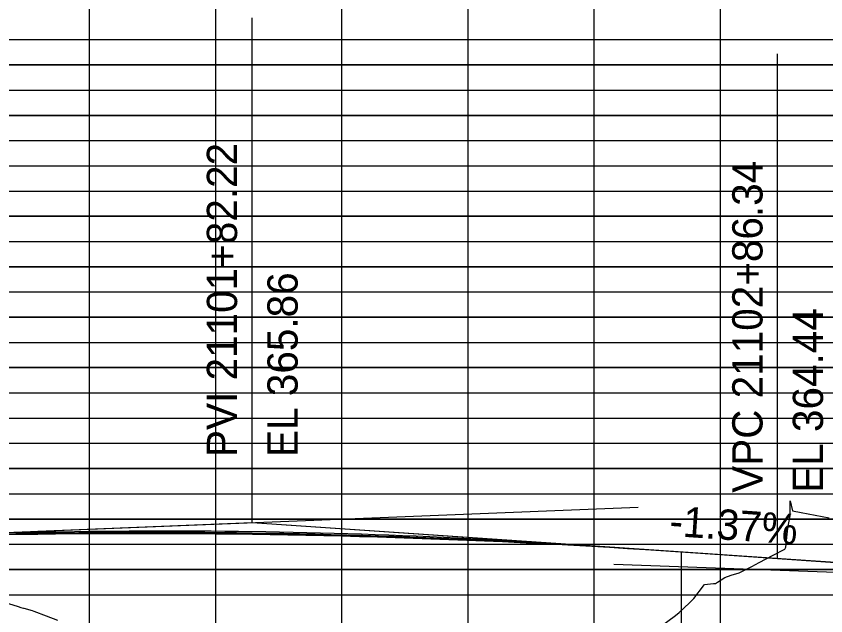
# Model space of a CAD drawing. Extents: x 1195880 to 1289360, y 2059330 to 2086925.
# Drawn here: x 1197141.8 to 1197302.3, y 2059661.6 to 2059780.4 of the extents above; entities that cross this region are included whole.
import ezdxf

# ---------------------------------------------------------------- set-up
doc = ezdxf.new("R2010")
doc.units = 0
for name, color, linetype in [('Default', 7, 'Continuous'), ('Existing Ground PGL', 7, 'Continuous'), ('Grid', 7, 'Continuous'), ('Profile', 7, 'Continuous'), ('Profile Annotation', 7, 'Continuous')]:
    doc.layers.add(name, color=color, linetype=linetype)

msp = doc.modelspace()

# ---------------------------------------------------------------- linework, layer by layer
for p, q in [((1197087.81, 2059676.01), (1197188.59, 2059680.04)), ((1197087.81, 2059676.01), (1197188.59, 2059680.04)), ((1197188.59, 2059680.04), (1197367.71, 2059667.81)), ((1197188.59, 2059680.04), (1197367.71, 2059667.81)), ((1197253.56, 2059675.6), (1197367.71, 2059667.81)), ((1197253.56, 2059675.6), (1197326.4, 2059670.63)), ((1197253.56, 2059675.6), (1197317.71, 2059671.22)), ((1197253.56, 2059675.6), (1197323.22, 2059670.85)), ((1197253.56, 2059675.6), (1197322.71, 2059670.88)), ((1197253.56, 2059675.6), (1197317.71, 2059671.22)), ((1197253.56, 2059675.6), (1197320.21, 2059671.05)), ((1197263.59, 2059674.92), (1197320.21, 2059671.05)), ((1197268.59, 2059674.58), (1197320.21, 2059671.05)), ((1197273.59, 2059674.23), (1197320.21, 2059671.05)), ((1197273.59, 2059674.23), (1197307.21, 2059671.94)), ((1197273.59, 2059674.23), (1197305.21, 2059672.08)), ((1197273.59, 2059674.23), (1197302.71, 2059672.25)), ((1197273.59, 2059674.23), (1197300.21, 2059672.42)), ((1197273.59, 2059674.23), (1197297.71, 2059672.59)), ((1197273.59, 2059674.23), (1197296.2, 2059672.69)), ((1197273.59, 2059674.23), (1197295.21, 2059672.76)), ((1197273.59, 2059674.23), (1197292.71, 2059672.93))]:
    msp.add_line(p, q)
for points in [[(1197138.59, 2059677.73), (1197141.92, 2059677.8), (1197145.26, 2059677.85), (1197148.59, 2059677.9), (1197151.92, 2059677.94), (1197155.26, 2059677.97), (1197158.59, 2059677.99), (1197161.92, 2059678.01), (1197165.26, 2059678.02), (1197168.59, 2059678.02), (1197171.92, 2059678.01), (1197175.26, 2059678), (1197178.59, 2059677.98), (1197181.92, 2059677.95), (1197185.26, 2059677.92), (1197191.92, 2059677.82), (1197195.26, 2059677.76), (1197198.59, 2059677.7), (1197201.92, 2059677.62), (1197205.26, 2059677.54), (1197208.59, 2059677.45), (1197211.92, 2059677.36), (1197215.26, 2059677.25), (1197218.59, 2059677.14), (1197221.92, 2059677.03), (1197225.26, 2059676.9), (1197228.59, 2059676.77), (1197231.92, 2059676.62), (1197235.26, 2059676.48), (1197238.59, 2059676.32), (1197241.92, 2059676.16), (1197245.26, 2059675.98), (1197248.59, 2059675.81), (1197251.92, 2059675.62), (1197255.26, 2059675.43), (1197258.59, 2059675.22), (1197261.92, 2059675.02), (1197265.26, 2059674.8), (1197268.59, 2059674.58)], [(1197139.01, 2059677.66), (1197142.55, 2059677.71), (1197146.09, 2059677.76), (1197149.63, 2059677.8), (1197153.17, 2059677.84), (1197156.71, 2059677.86), (1197160.26, 2059677.88), (1197163.8, 2059677.89), (1197167.34, 2059677.89), (1197170.88, 2059677.89), (1197174.42, 2059677.87), (1197177.96, 2059677.85), (1197181.51, 2059677.82), (1197185.05, 2059677.78), (1197192.13, 2059677.68), (1197195.67, 2059677.62), (1197199.21, 2059677.55), (1197202.76, 2059677.47), (1197206.3, 2059677.39), (1197209.84, 2059677.29), (1197213.38, 2059677.19), (1197216.92, 2059677.08), (1197220.46, 2059676.96), (1197224.01, 2059676.84), (1197227.55, 2059676.7), (1197231.09, 2059676.56), (1197234.63, 2059676.41), (1197238.17, 2059676.25), (1197241.71, 2059676.09), (1197245.26, 2059675.91), (1197248.8, 2059675.73), (1197252.34, 2059675.54), (1197255.88, 2059675.34), (1197259.42, 2059675.14), (1197262.96, 2059674.92), (1197266.51, 2059674.7), (1197270.05, 2059674.47), (1197273.59, 2059674.23)], [(1197139.01, 2059677.66), (1197142.55, 2059677.71), (1197146.09, 2059677.76), (1197149.63, 2059677.8), (1197153.17, 2059677.84), (1197156.71, 2059677.86), (1197160.26, 2059677.88), (1197163.8, 2059677.89), (1197167.34, 2059677.89), (1197170.88, 2059677.89), (1197174.42, 2059677.87), (1197177.96, 2059677.85), (1197181.51, 2059677.82), (1197185.05, 2059677.78), (1197192.13, 2059677.68), (1197195.67, 2059677.62), (1197199.21, 2059677.55), (1197202.76, 2059677.47), (1197206.3, 2059677.39), (1197209.84, 2059677.29), (1197213.38, 2059677.19), (1197216.92, 2059677.08), (1197220.46, 2059676.96), (1197224.01, 2059676.84), (1197227.55, 2059676.7), (1197231.09, 2059676.56), (1197234.63, 2059676.41), (1197238.17, 2059676.25), (1197241.71, 2059676.09), (1197245.26, 2059675.91), (1197248.8, 2059675.73), (1197252.34, 2059675.54), (1197255.88, 2059675.34), (1197259.42, 2059675.14), (1197262.96, 2059674.92), (1197266.51, 2059674.7), (1197270.05, 2059674.47), (1197273.59, 2059674.23)], [(1197139.01, 2059677.66), (1197142.55, 2059677.71), (1197146.09, 2059677.76), (1197149.63, 2059677.8), (1197153.17, 2059677.84), (1197156.71, 2059677.86), (1197160.26, 2059677.88), (1197163.8, 2059677.89), (1197167.34, 2059677.89), (1197170.88, 2059677.89), (1197174.42, 2059677.87), (1197177.96, 2059677.85), (1197181.51, 2059677.82), (1197185.05, 2059677.78), (1197192.13, 2059677.68), (1197195.67, 2059677.62), (1197199.21, 2059677.55), (1197202.76, 2059677.47), (1197206.3, 2059677.39), (1197209.84, 2059677.29), (1197213.38, 2059677.19), (1197216.92, 2059677.08), (1197220.46, 2059676.96), (1197224.01, 2059676.84), (1197227.55, 2059676.7), (1197231.09, 2059676.56), (1197234.63, 2059676.41), (1197238.17, 2059676.25), (1197241.71, 2059676.09), (1197245.26, 2059675.91), (1197248.8, 2059675.73), (1197252.34, 2059675.54), (1197255.88, 2059675.34), (1197259.42, 2059675.14), (1197262.96, 2059674.92), (1197266.51, 2059674.7), (1197270.05, 2059674.47), (1197273.59, 2059674.23)], [(1197139.01, 2059677.66), (1197142.55, 2059677.71), (1197146.09, 2059677.76), (1197149.63, 2059677.8), (1197153.17, 2059677.84), (1197156.71, 2059677.86), (1197160.26, 2059677.88), (1197163.8, 2059677.89), (1197167.34, 2059677.89), (1197170.88, 2059677.89), (1197174.42, 2059677.87), (1197177.96, 2059677.85), (1197181.51, 2059677.82), (1197185.05, 2059677.78), (1197192.13, 2059677.68), (1197195.67, 2059677.62), (1197199.21, 2059677.55), (1197202.76, 2059677.47), (1197206.3, 2059677.39), (1197209.84, 2059677.29), (1197213.38, 2059677.19), (1197216.92, 2059677.08), (1197220.46, 2059676.96), (1197224.01, 2059676.84), (1197227.55, 2059676.7), (1197231.09, 2059676.56), (1197234.63, 2059676.41), (1197238.17, 2059676.25), (1197241.71, 2059676.09), (1197245.26, 2059675.91), (1197248.8, 2059675.73), (1197252.34, 2059675.54), (1197255.88, 2059675.34), (1197259.42, 2059675.14), (1197262.96, 2059674.92), (1197266.51, 2059674.7), (1197270.05, 2059674.47), (1197273.59, 2059674.23)], [(1197139.01, 2059677.66), (1197142.55, 2059677.71), (1197146.09, 2059677.76), (1197149.63, 2059677.8), (1197153.17, 2059677.84), (1197156.71, 2059677.86), (1197160.26, 2059677.88), (1197163.8, 2059677.89), (1197167.34, 2059677.89), (1197170.88, 2059677.89), (1197174.42, 2059677.87), (1197177.96, 2059677.85), (1197181.51, 2059677.82), (1197185.05, 2059677.78), (1197192.13, 2059677.68), (1197195.67, 2059677.62), (1197199.21, 2059677.55), (1197202.76, 2059677.47), (1197206.3, 2059677.39), (1197209.84, 2059677.29), (1197213.38, 2059677.19), (1197216.92, 2059677.08), (1197220.46, 2059676.96), (1197224.01, 2059676.84), (1197227.55, 2059676.7), (1197231.09, 2059676.56), (1197234.63, 2059676.41), (1197238.17, 2059676.25), (1197241.71, 2059676.09), (1197245.26, 2059675.91), (1197248.8, 2059675.73), (1197252.34, 2059675.54), (1197255.88, 2059675.34), (1197259.42, 2059675.14), (1197262.96, 2059674.92), (1197266.51, 2059674.7), (1197270.05, 2059674.47), (1197273.59, 2059674.23)], [(1197139.01, 2059677.66), (1197142.55, 2059677.71), (1197146.09, 2059677.76), (1197149.63, 2059677.8), (1197153.17, 2059677.84), (1197156.71, 2059677.86), (1197160.26, 2059677.88), (1197163.8, 2059677.89), (1197167.34, 2059677.89), (1197170.88, 2059677.89), (1197174.42, 2059677.87), (1197177.96, 2059677.85), (1197181.51, 2059677.82), (1197185.05, 2059677.78), (1197192.13, 2059677.68), (1197195.67, 2059677.62), (1197199.21, 2059677.55), (1197202.76, 2059677.47), (1197206.3, 2059677.39), (1197209.84, 2059677.29), (1197213.38, 2059677.19), (1197216.92, 2059677.08), (1197220.46, 2059676.96), (1197224.01, 2059676.84), (1197227.55, 2059676.7), (1197231.09, 2059676.56), (1197234.63, 2059676.41), (1197238.17, 2059676.25), (1197241.71, 2059676.09), (1197245.26, 2059675.91), (1197248.8, 2059675.73), (1197252.34, 2059675.54), (1197255.88, 2059675.34), (1197259.42, 2059675.14), (1197262.96, 2059674.92), (1197266.51, 2059674.7), (1197270.05, 2059674.47), (1197273.59, 2059674.23)], [(1197139.01, 2059677.66), (1197142.55, 2059677.71), (1197146.09, 2059677.76), (1197149.63, 2059677.8), (1197153.17, 2059677.84), (1197156.71, 2059677.86), (1197160.26, 2059677.88), (1197163.8, 2059677.89), (1197167.34, 2059677.89), (1197170.88, 2059677.89), (1197174.42, 2059677.87), (1197177.96, 2059677.85), (1197181.51, 2059677.82), (1197185.05, 2059677.78), (1197192.13, 2059677.68), (1197195.67, 2059677.62), (1197199.21, 2059677.55), (1197202.76, 2059677.47), (1197206.3, 2059677.39), (1197209.84, 2059677.29), (1197213.38, 2059677.19), (1197216.92, 2059677.08), (1197220.46, 2059676.96), (1197224.01, 2059676.84), (1197227.55, 2059676.7), (1197231.09, 2059676.56), (1197234.63, 2059676.41), (1197238.17, 2059676.25), (1197241.71, 2059676.09), (1197245.26, 2059675.91), (1197248.8, 2059675.73), (1197252.34, 2059675.54), (1197255.88, 2059675.34), (1197259.42, 2059675.14), (1197262.96, 2059674.92), (1197266.51, 2059674.7), (1197270.05, 2059674.47), (1197273.59, 2059674.23)], [(1197139.01, 2059677.66), (1197142.55, 2059677.71), (1197146.09, 2059677.76), (1197149.63, 2059677.8), (1197153.17, 2059677.84), (1197156.71, 2059677.86), (1197160.26, 2059677.88), (1197163.8, 2059677.89), (1197167.34, 2059677.89), (1197170.88, 2059677.89), (1197174.42, 2059677.87), (1197177.96, 2059677.85), (1197181.51, 2059677.82), (1197185.05, 2059677.78), (1197192.13, 2059677.68), (1197195.67, 2059677.62), (1197199.21, 2059677.55), (1197202.76, 2059677.47), (1197206.3, 2059677.39), (1197209.84, 2059677.29), (1197213.38, 2059677.19), (1197216.92, 2059677.08), (1197220.46, 2059676.96), (1197224.01, 2059676.84), (1197227.55, 2059676.7), (1197231.09, 2059676.56), (1197234.63, 2059676.41), (1197238.17, 2059676.25), (1197241.71, 2059676.09), (1197245.26, 2059675.91), (1197248.8, 2059675.73), (1197252.34, 2059675.54), (1197255.88, 2059675.34), (1197259.42, 2059675.14), (1197262.96, 2059674.92), (1197266.51, 2059674.7), (1197270.05, 2059674.47), (1197273.59, 2059674.23)], [(1197139.01, 2059677.66), (1197142.55, 2059677.71), (1197146.09, 2059677.76), (1197149.63, 2059677.8), (1197153.17, 2059677.84), (1197156.71, 2059677.86), (1197160.26, 2059677.88), (1197163.8, 2059677.89), (1197167.34, 2059677.89), (1197170.88, 2059677.89), (1197174.42, 2059677.87), (1197177.96, 2059677.85), (1197181.51, 2059677.82), (1197185.05, 2059677.78), (1197192.13, 2059677.68), (1197195.67, 2059677.62), (1197199.21, 2059677.55), (1197202.76, 2059677.47), (1197206.3, 2059677.39), (1197209.84, 2059677.29), (1197213.38, 2059677.19), (1197216.92, 2059677.08), (1197220.46, 2059676.96), (1197224.01, 2059676.84), (1197227.55, 2059676.7), (1197231.09, 2059676.56), (1197234.63, 2059676.41), (1197238.17, 2059676.25), (1197241.71, 2059676.09), (1197245.26, 2059675.91), (1197248.8, 2059675.73), (1197252.34, 2059675.54), (1197255.88, 2059675.34), (1197259.42, 2059675.14), (1197262.96, 2059674.92), (1197266.51, 2059674.7), (1197270.05, 2059674.47), (1197273.59, 2059674.23)], [(1197139.86, 2059677.98), (1197142.57, 2059678.05), (1197145.28, 2059678.11), (1197147.98, 2059678.17), (1197150.69, 2059678.22), (1197153.4, 2059678.26), (1197156.11, 2059678.3), (1197158.81, 2059678.33), (1197161.52, 2059678.36), (1197164.23, 2059678.38), (1197166.93, 2059678.39), (1197169.64, 2059678.4), (1197172.35, 2059678.4), (1197175.05, 2059678.39), (1197177.76, 2059678.38), (1197180.47, 2059678.37), (1197183.18, 2059678.34), (1197185.88, 2059678.31), (1197191.3, 2059678.24), (1197194, 2059678.19), (1197196.71, 2059678.14), (1197199.42, 2059678.08), (1197202.12, 2059678.01), (1197204.83, 2059677.94), (1197207.54, 2059677.86), (1197210.25, 2059677.78), (1197212.95, 2059677.69), (1197215.66, 2059677.59), (1197218.37, 2059677.49), (1197221.07, 2059677.38), (1197223.78, 2059677.27), (1197226.49, 2059677.15), (1197229.19, 2059677.02), (1197231.9, 2059676.89), (1197234.61, 2059676.75), (1197237.32, 2059676.6), (1197240.02, 2059676.45), (1197242.73, 2059676.29), (1197245.44, 2059676.13), (1197248.14, 2059675.96), (1197250.85, 2059675.78), (1197253.56, 2059675.6)], [(1197139.86, 2059677.98), (1197142.57, 2059678.05), (1197145.28, 2059678.11), (1197147.98, 2059678.17), (1197150.69, 2059678.22), (1197153.4, 2059678.26), (1197156.11, 2059678.3), (1197158.81, 2059678.33), (1197161.52, 2059678.36), (1197164.23, 2059678.38), (1197166.93, 2059678.39), (1197169.64, 2059678.4), (1197172.35, 2059678.4), (1197175.05, 2059678.39), (1197177.76, 2059678.38), (1197180.47, 2059678.37), (1197183.18, 2059678.34), (1197185.88, 2059678.31), (1197191.3, 2059678.24), (1197194, 2059678.19), (1197196.71, 2059678.14), (1197199.42, 2059678.08), (1197202.12, 2059678.01), (1197204.83, 2059677.94), (1197207.54, 2059677.86), (1197210.25, 2059677.78), (1197212.95, 2059677.69), (1197215.66, 2059677.59), (1197218.37, 2059677.49), (1197221.07, 2059677.38), (1197223.78, 2059677.27), (1197226.49, 2059677.15), (1197229.19, 2059677.02), (1197231.9, 2059676.89), (1197234.61, 2059676.75), (1197237.32, 2059676.6), (1197240.02, 2059676.45), (1197242.73, 2059676.29), (1197245.44, 2059676.13), (1197248.14, 2059675.96), (1197250.85, 2059675.78), (1197253.56, 2059675.6)], [(1197139.86, 2059677.98), (1197142.57, 2059678.05), (1197145.28, 2059678.11), (1197147.98, 2059678.17), (1197150.69, 2059678.22), (1197153.4, 2059678.26), (1197156.11, 2059678.3), (1197158.81, 2059678.33), (1197161.52, 2059678.36), (1197164.23, 2059678.38), (1197166.93, 2059678.39), (1197169.64, 2059678.4), (1197172.35, 2059678.4), (1197175.05, 2059678.39), (1197177.76, 2059678.38), (1197180.47, 2059678.37), (1197183.18, 2059678.34), (1197185.88, 2059678.31), (1197191.3, 2059678.24), (1197194, 2059678.19), (1197196.71, 2059678.14), (1197199.42, 2059678.08), (1197202.12, 2059678.01), (1197204.83, 2059677.94), (1197207.54, 2059677.86), (1197210.25, 2059677.78), (1197212.95, 2059677.69), (1197215.66, 2059677.59), (1197218.37, 2059677.49), (1197221.07, 2059677.38), (1197223.78, 2059677.27), (1197226.49, 2059677.15), (1197229.19, 2059677.02), (1197231.9, 2059676.89), (1197234.61, 2059676.75), (1197237.32, 2059676.6), (1197240.02, 2059676.45), (1197242.73, 2059676.29), (1197245.44, 2059676.13), (1197248.14, 2059675.96), (1197250.85, 2059675.78), (1197253.56, 2059675.6)], [(1197139.86, 2059677.98), (1197142.57, 2059678.05), (1197145.28, 2059678.11), (1197147.98, 2059678.17), (1197150.69, 2059678.22), (1197153.4, 2059678.26), (1197156.11, 2059678.3), (1197158.81, 2059678.33), (1197161.52, 2059678.36), (1197164.23, 2059678.38), (1197166.93, 2059678.39), (1197169.64, 2059678.4), (1197172.35, 2059678.4), (1197175.05, 2059678.39), (1197177.76, 2059678.38), (1197180.47, 2059678.37), (1197183.18, 2059678.34), (1197185.88, 2059678.31), (1197191.3, 2059678.24), (1197194, 2059678.19), (1197196.71, 2059678.14), (1197199.42, 2059678.08), (1197202.12, 2059678.01), (1197204.83, 2059677.94), (1197207.54, 2059677.86), (1197210.25, 2059677.78), (1197212.95, 2059677.69), (1197215.66, 2059677.59), (1197218.37, 2059677.49), (1197221.07, 2059677.38), (1197223.78, 2059677.27), (1197226.49, 2059677.15), (1197229.19, 2059677.02), (1197231.9, 2059676.89), (1197234.61, 2059676.75), (1197237.32, 2059676.6), (1197240.02, 2059676.45), (1197242.73, 2059676.29), (1197245.44, 2059676.13), (1197248.14, 2059675.96), (1197250.85, 2059675.78), (1197253.56, 2059675.6)], [(1197139.86, 2059677.98), (1197142.57, 2059678.05), (1197145.28, 2059678.11), (1197147.98, 2059678.17), (1197150.69, 2059678.22), (1197153.4, 2059678.26), (1197156.11, 2059678.3), (1197158.81, 2059678.33), (1197161.52, 2059678.36), (1197164.23, 2059678.38), (1197166.93, 2059678.39), (1197169.64, 2059678.4), (1197172.35, 2059678.4), (1197175.05, 2059678.39), (1197177.76, 2059678.38), (1197180.47, 2059678.37), (1197183.18, 2059678.34), (1197185.88, 2059678.31), (1197191.3, 2059678.24), (1197194, 2059678.19), (1197196.71, 2059678.14), (1197199.42, 2059678.08), (1197202.12, 2059678.01), (1197204.83, 2059677.94), (1197207.54, 2059677.86), (1197210.25, 2059677.78), (1197212.95, 2059677.69), (1197215.66, 2059677.59), (1197218.37, 2059677.49), (1197221.07, 2059677.38), (1197223.78, 2059677.27), (1197226.49, 2059677.15), (1197229.19, 2059677.02), (1197231.9, 2059676.89), (1197234.61, 2059676.75), (1197237.32, 2059676.6), (1197240.02, 2059676.45), (1197242.73, 2059676.29), (1197245.44, 2059676.13), (1197248.14, 2059675.96), (1197250.85, 2059675.78), (1197253.56, 2059675.6)], [(1197139.86, 2059677.98), (1197142.57, 2059678.05), (1197145.28, 2059678.11), (1197147.98, 2059678.17), (1197150.69, 2059678.22), (1197153.4, 2059678.26), (1197156.11, 2059678.3), (1197158.81, 2059678.33), (1197161.52, 2059678.36), (1197164.23, 2059678.38), (1197166.93, 2059678.39), (1197169.64, 2059678.4), (1197172.35, 2059678.4), (1197175.05, 2059678.39), (1197177.76, 2059678.38), (1197180.47, 2059678.37), (1197183.18, 2059678.34), (1197185.88, 2059678.31), (1197191.3, 2059678.24), (1197194, 2059678.19), (1197196.71, 2059678.14), (1197199.42, 2059678.08), (1197202.12, 2059678.01), (1197204.83, 2059677.94), (1197207.54, 2059677.86), (1197210.25, 2059677.78), (1197212.95, 2059677.69), (1197215.66, 2059677.59), (1197218.37, 2059677.49), (1197221.07, 2059677.38), (1197223.78, 2059677.27), (1197226.49, 2059677.15), (1197229.19, 2059677.02), (1197231.9, 2059676.89), (1197234.61, 2059676.75), (1197237.32, 2059676.6), (1197240.02, 2059676.45), (1197242.73, 2059676.29), (1197245.44, 2059676.13), (1197248.14, 2059675.96), (1197250.85, 2059675.78), (1197253.56, 2059675.6)], [(1197139.86, 2059677.98), (1197142.57, 2059678.05), (1197145.28, 2059678.11), (1197147.98, 2059678.17), (1197150.69, 2059678.22), (1197153.4, 2059678.26), (1197156.11, 2059678.3), (1197158.81, 2059678.33), (1197161.52, 2059678.36), (1197164.23, 2059678.38), (1197166.93, 2059678.39), (1197169.64, 2059678.4), (1197172.35, 2059678.4), (1197175.05, 2059678.39), (1197177.76, 2059678.38), (1197180.47, 2059678.37), (1197183.18, 2059678.34), (1197185.88, 2059678.31), (1197191.3, 2059678.24), (1197194, 2059678.19), (1197196.71, 2059678.14), (1197199.42, 2059678.08), (1197202.12, 2059678.01), (1197204.83, 2059677.94), (1197207.54, 2059677.86), (1197210.25, 2059677.78), (1197212.95, 2059677.69), (1197215.66, 2059677.59), (1197218.37, 2059677.49), (1197221.07, 2059677.38), (1197223.78, 2059677.27), (1197226.49, 2059677.15), (1197229.19, 2059677.02), (1197231.9, 2059676.89), (1197234.61, 2059676.75), (1197237.32, 2059676.6), (1197240.02, 2059676.45), (1197242.73, 2059676.29), (1197245.44, 2059676.13), (1197248.14, 2059675.96), (1197250.85, 2059675.78), (1197253.56, 2059675.6)], [(1197141.71, 2059677.88), (1197144.84, 2059677.94), (1197147.96, 2059677.99), (1197151.09, 2059678.03), (1197154.21, 2059678.07), (1197157.34, 2059678.1), (1197160.46, 2059678.12), (1197163.59, 2059678.14), (1197166.71, 2059678.14), (1197169.84, 2059678.15), (1197172.96, 2059678.14), (1197176.09, 2059678.13), (1197179.21, 2059678.11), (1197182.34, 2059678.08), (1197185.46, 2059678.05), (1197191.71, 2059677.96), (1197194.84, 2059677.91), (1197197.96, 2059677.84), (1197201.09, 2059677.77), (1197204.21, 2059677.7), (1197207.34, 2059677.62), (1197210.46, 2059677.53), (1197213.59, 2059677.43), (1197216.71, 2059677.32), (1197219.84, 2059677.21), (1197222.96, 2059677.1), (1197226.09, 2059676.97), (1197229.21, 2059676.84), (1197232.34, 2059676.7), (1197235.46, 2059676.55), (1197238.59, 2059676.4), (1197241.71, 2059676.24), (1197244.84, 2059676.07), (1197247.96, 2059675.9), (1197251.09, 2059675.71), (1197254.21, 2059675.53), (1197257.34, 2059675.33), (1197260.46, 2059675.13), (1197263.59, 2059674.92)], [(1197292.71, 2059672.93), (1197295.83, 2059672.72), (1197298.96, 2059672.51), (1197302.08, 2059672.3), (1197305.21, 2059672.09)], [(1197295.21, 2059672.76), (1197298.23, 2059672.55), (1197301.25, 2059672.35), (1197304.27, 2059672.15)], [(1197296.2, 2059672.69), (1197299.18, 2059672.49), (1197302.16, 2059672.29), (1197305.14, 2059672.09)], [(1197297.71, 2059672.59), (1197300.63, 2059672.39), (1197303.54, 2059672.19)], [(1197300.21, 2059672.42), (1197303.02, 2059672.23)]]:
    msp.add_lwpolyline(points)
at = {"layer": 'Default'}
for p, q in [((1197070.02, 2059675.3), (1197265.1, 2059683.1)), ((1197516.64, 2059662.37), (1197260.22, 2059671.73))]:
    msp.add_line(p, q, dxfattribs=at)
at = {"layer": 'Existing Ground PGL'}
for points in [[(1197269.67, 2059659.56), (1197272.44, 2059661.63), (1197273.19, 2059662.19), (1197275.22, 2059664.14), (1197276.13, 2059665.01), (1197277.99, 2059667.5), (1197278.19, 2059667.77), (1197280, 2059667.97), (1197280.38, 2059667.99), (1197280.76, 2059668.24), (1197282.21, 2059669.18), (1197283.53, 2059669.59), (1197285.1, 2059670.07), (1197286.3, 2059670.69), (1197287.56, 2059671.32), (1197289.07, 2059672.13), (1197291.85, 2059673.59), (1197294.13, 2059674.79), (1197294.34, 2059675.14), (1197294.62, 2059677.76), (1197294.74, 2059678.9), (1197295.18, 2059681.34), (1197295.19, 2059684.37), (1197295.68, 2059682.38), (1197297.39, 2059682.04), (1197300.16, 2059681.51), (1197302.93, 2059681)], [(1197139.41, 2059664.24), (1197142.18, 2059663.39), (1197142.76, 2059663.21), (1197143.24, 2059663.07), (1197143.32, 2059663.06), (1197144.95, 2059662.6), (1197145.31, 2059662.5), (1197147.72, 2059661.56), (1197150, 2059660.67)]]:
    msp.add_lwpolyline(points, dxfattribs=at)
at = {"layer": 'Grid'}
for p, q in [((1197156.37, 2059350.74), (1197156.37, 2059950.74)), ((1197181.37, 2059350.74), (1197181.37, 2059950.74)), ((1197206.37, 2059350.74), (1197206.37, 2059950.74)), ((1197231.37, 2059350.74), (1197231.37, 2059950.74)), ((1197256.37, 2059350.74), (1197256.37, 2059950.74)), ((1197281.37, 2059350.74), (1197281.37, 2059950.74)), ((1197006.37, 2059775.74), (1198006.37, 2059775.74)), ((1197006.37, 2059770.74), (1198006.37, 2059770.74)), ((1198006.37, 2059770.74), (1197006.37, 2059770.74)), ((1197006.37, 2059765.74), (1198006.37, 2059765.74)), ((1197006.37, 2059760.74), (1198006.37, 2059760.74)), ((1198006.37, 2059760.74), (1197006.37, 2059760.74)), ((1197006.37, 2059755.74), (1198006.37, 2059755.74)), ((1197006.37, 2059750.74), (1198006.37, 2059750.74)), ((1197006.37, 2059745.74), (1198006.37, 2059745.74)), ((1197006.37, 2059740.74), (1198006.37, 2059740.74)), ((1198006.37, 2059740.74), (1197006.37, 2059740.74)), ((1197006.37, 2059735.74), (1198006.37, 2059735.74)), ((1197006.37, 2059730.74), (1198006.37, 2059730.74)), ((1198006.37, 2059730.74), (1197006.37, 2059730.74)), ((1197006.37, 2059725.74), (1198006.37, 2059725.74)), ((1197006.37, 2059720.74), (1198006.37, 2059720.74)), ((1198006.37, 2059720.74), (1197006.37, 2059720.74)), ((1197006.37, 2059715.74), (1198006.37, 2059715.74)), ((1197006.37, 2059710.74), (1198006.37, 2059710.74)), ((1198006.37, 2059710.74), (1197006.37, 2059710.74)), ((1197006.37, 2059705.74), (1198006.37, 2059705.74)), ((1197006.37, 2059700.74), (1198006.37, 2059700.74)), ((1197006.37, 2059695.74), (1198006.37, 2059695.74)), ((1197006.37, 2059690.74), (1198006.37, 2059690.74)), ((1198006.37, 2059690.74), (1197006.37, 2059690.74)), ((1197006.37, 2059685.74), (1198006.37, 2059685.74)), ((1197006.37, 2059680.74), (1198006.37, 2059680.74)), ((1198006.37, 2059680.74), (1197006.37, 2059680.74)), ((1197006.37, 2059675.74), (1198006.37, 2059675.74)), ((1197006.37, 2059670.74), (1198006.37, 2059670.74)), ((1198006.37, 2059670.74), (1197006.37, 2059670.74)), ((1197006.37, 2059665.74), (1198006.37, 2059665.74))]:
    msp.add_line(p, q, dxfattribs=at)
at = {"layer": 'Profile'}
msp.add_line((1197273.59, 2059674.23), (1197292.71, 2059672.93), dxfattribs=at)
for points in [[(1197139.01, 2059677.66), (1197142.55, 2059677.71), (1197146.09, 2059677.76), (1197149.63, 2059677.8), (1197153.17, 2059677.84), (1197156.71, 2059677.86), (1197160.26, 2059677.88), (1197163.8, 2059677.89), (1197167.34, 2059677.89), (1197170.88, 2059677.89), (1197174.42, 2059677.87), (1197177.96, 2059677.85), (1197181.51, 2059677.82), (1197185.05, 2059677.78), (1197192.13, 2059677.68), (1197195.67, 2059677.62), (1197199.21, 2059677.55), (1197202.76, 2059677.47), (1197206.3, 2059677.39), (1197209.84, 2059677.29), (1197213.38, 2059677.19), (1197216.92, 2059677.08), (1197220.46, 2059676.96), (1197224.01, 2059676.84), (1197227.55, 2059676.7), (1197231.09, 2059676.56), (1197234.63, 2059676.41), (1197238.17, 2059676.25), (1197241.71, 2059676.09), (1197245.26, 2059675.91), (1197248.8, 2059675.73), (1197252.34, 2059675.54), (1197255.88, 2059675.34), (1197259.42, 2059675.14), (1197262.96, 2059674.92), (1197266.51, 2059674.7), (1197270.05, 2059674.47), (1197273.59, 2059674.23)], [(1197292.71, 2059672.93), (1197295.83, 2059672.72), (1197298.96, 2059672.51), (1197302.08, 2059672.3), (1197305.21, 2059672.09)]]:
    msp.add_lwpolyline(points, dxfattribs=at)
at = {"layer": 'Profile Annotation'}
for p, q in [((1197188.59, 2059680.04), (1197188.59, 2059780.04)), ((1197292.71, 2059672.93), (1197292.71, 2059772.93)), ((1197146.09, 2059678.34), (1197188.59, 2059680.04)), ((1197188.59, 2059680.04), (1197231.09, 2059677.14)), ((1197273.59, 2059674.23), (1197273.59, 2059574.23))]:
    msp.add_line(p, q, dxfattribs=at)

# ---------------------------------------------------------------- texts
for s, rotation, p in [('PVI 21101+82.22', 90, (1197185.59, 2059693.04)), ('VPC 21102+86.34', 90, (1197289.71, 2059685.93)), ('EL 365.86', 90, (1197197.59, 2059693.04)), ('EL 364.44', 90, (1197301.71, 2059685.93)), ('-1.37%', 356.0939, (1197271.12, 2059677.41))]:
    msp.add_text(s, height=6, rotation=rotation, dxfattribs=at).set_placement(p)

doc.saveas('drawing.dxf')
